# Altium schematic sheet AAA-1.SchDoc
size 594 x 420 mm
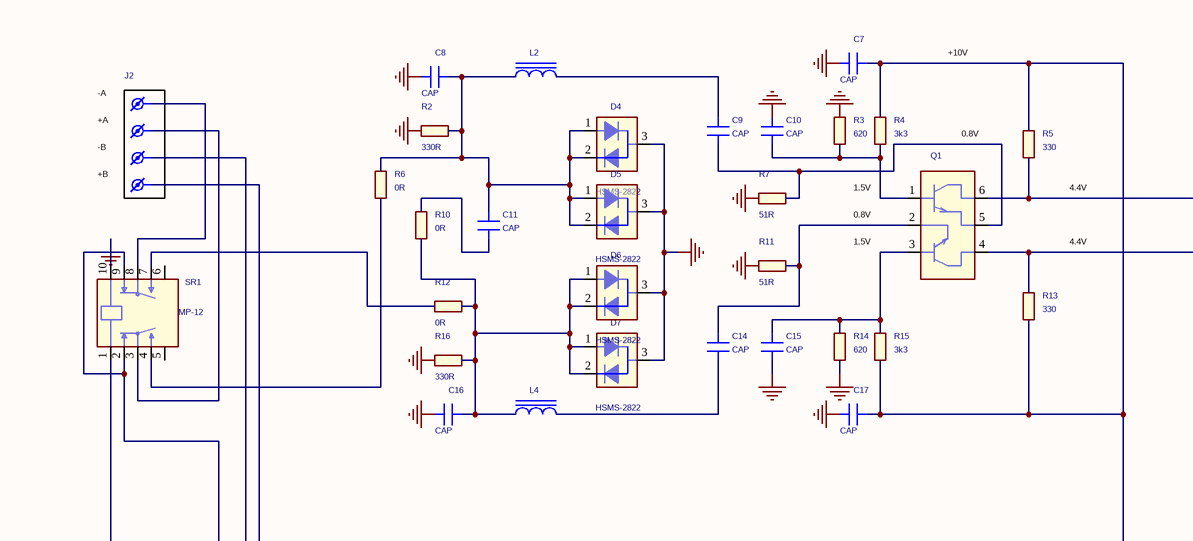
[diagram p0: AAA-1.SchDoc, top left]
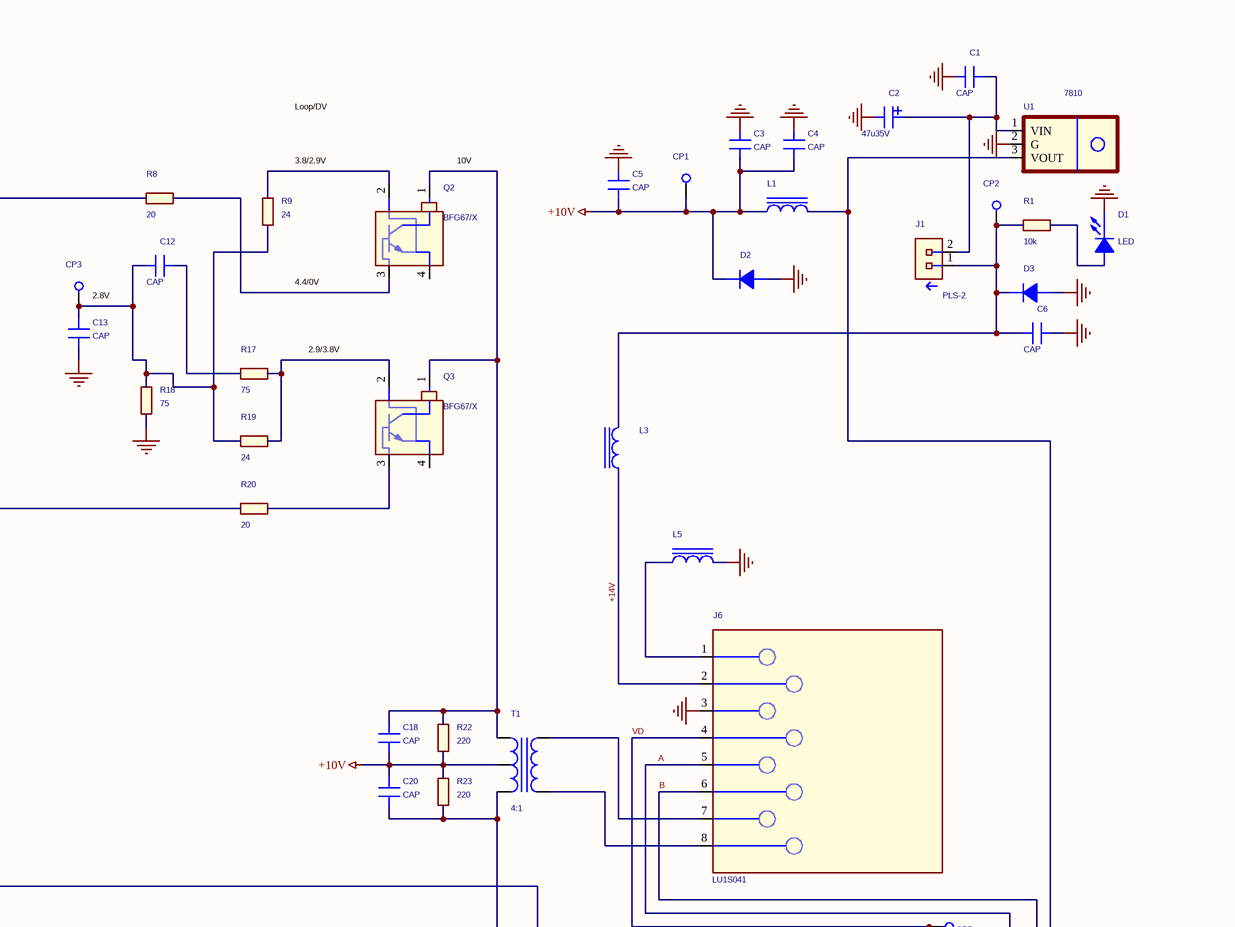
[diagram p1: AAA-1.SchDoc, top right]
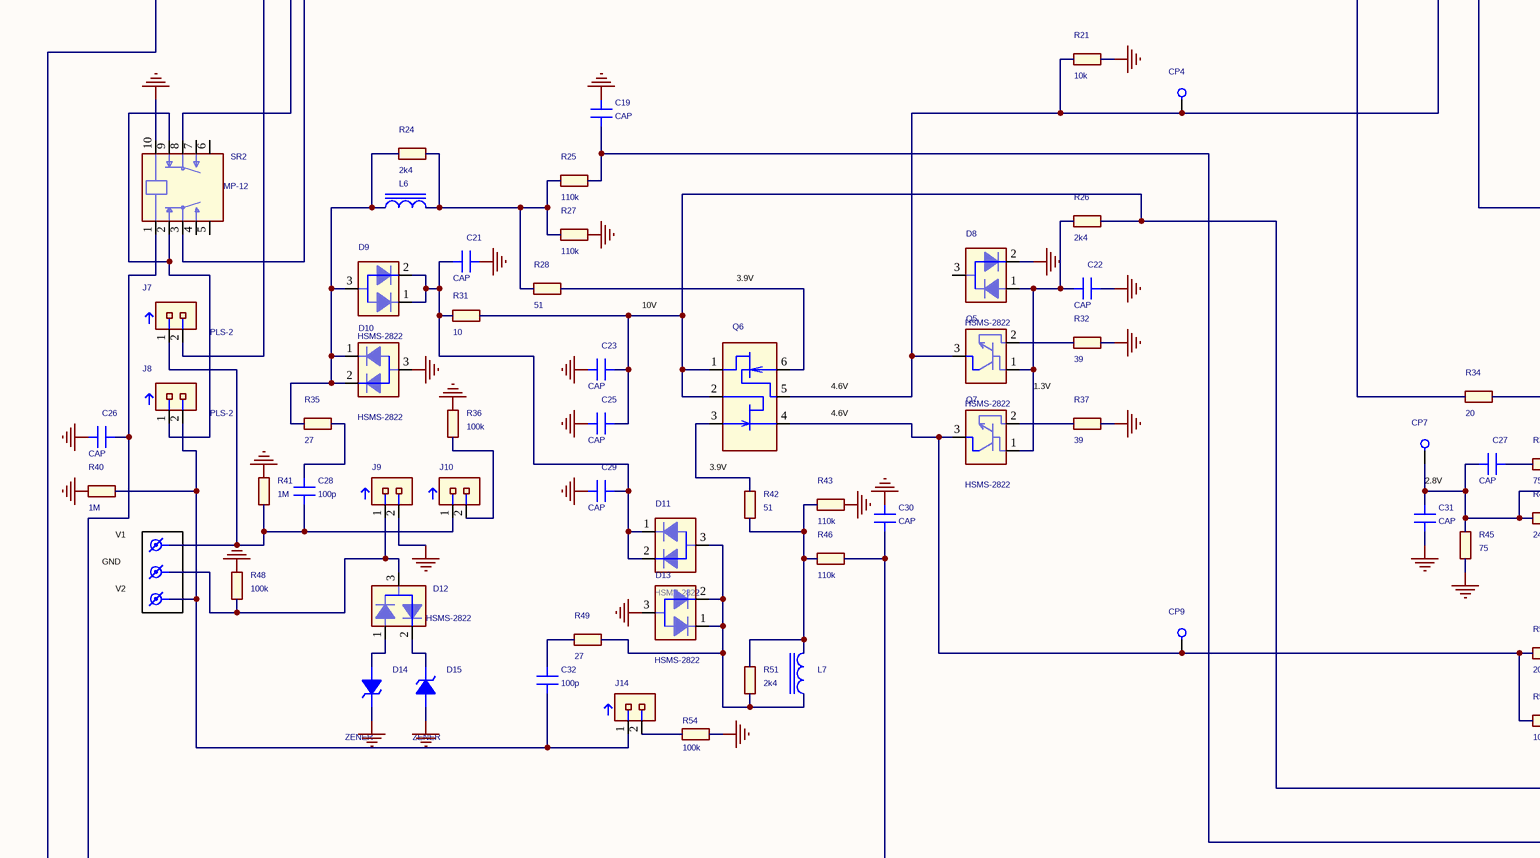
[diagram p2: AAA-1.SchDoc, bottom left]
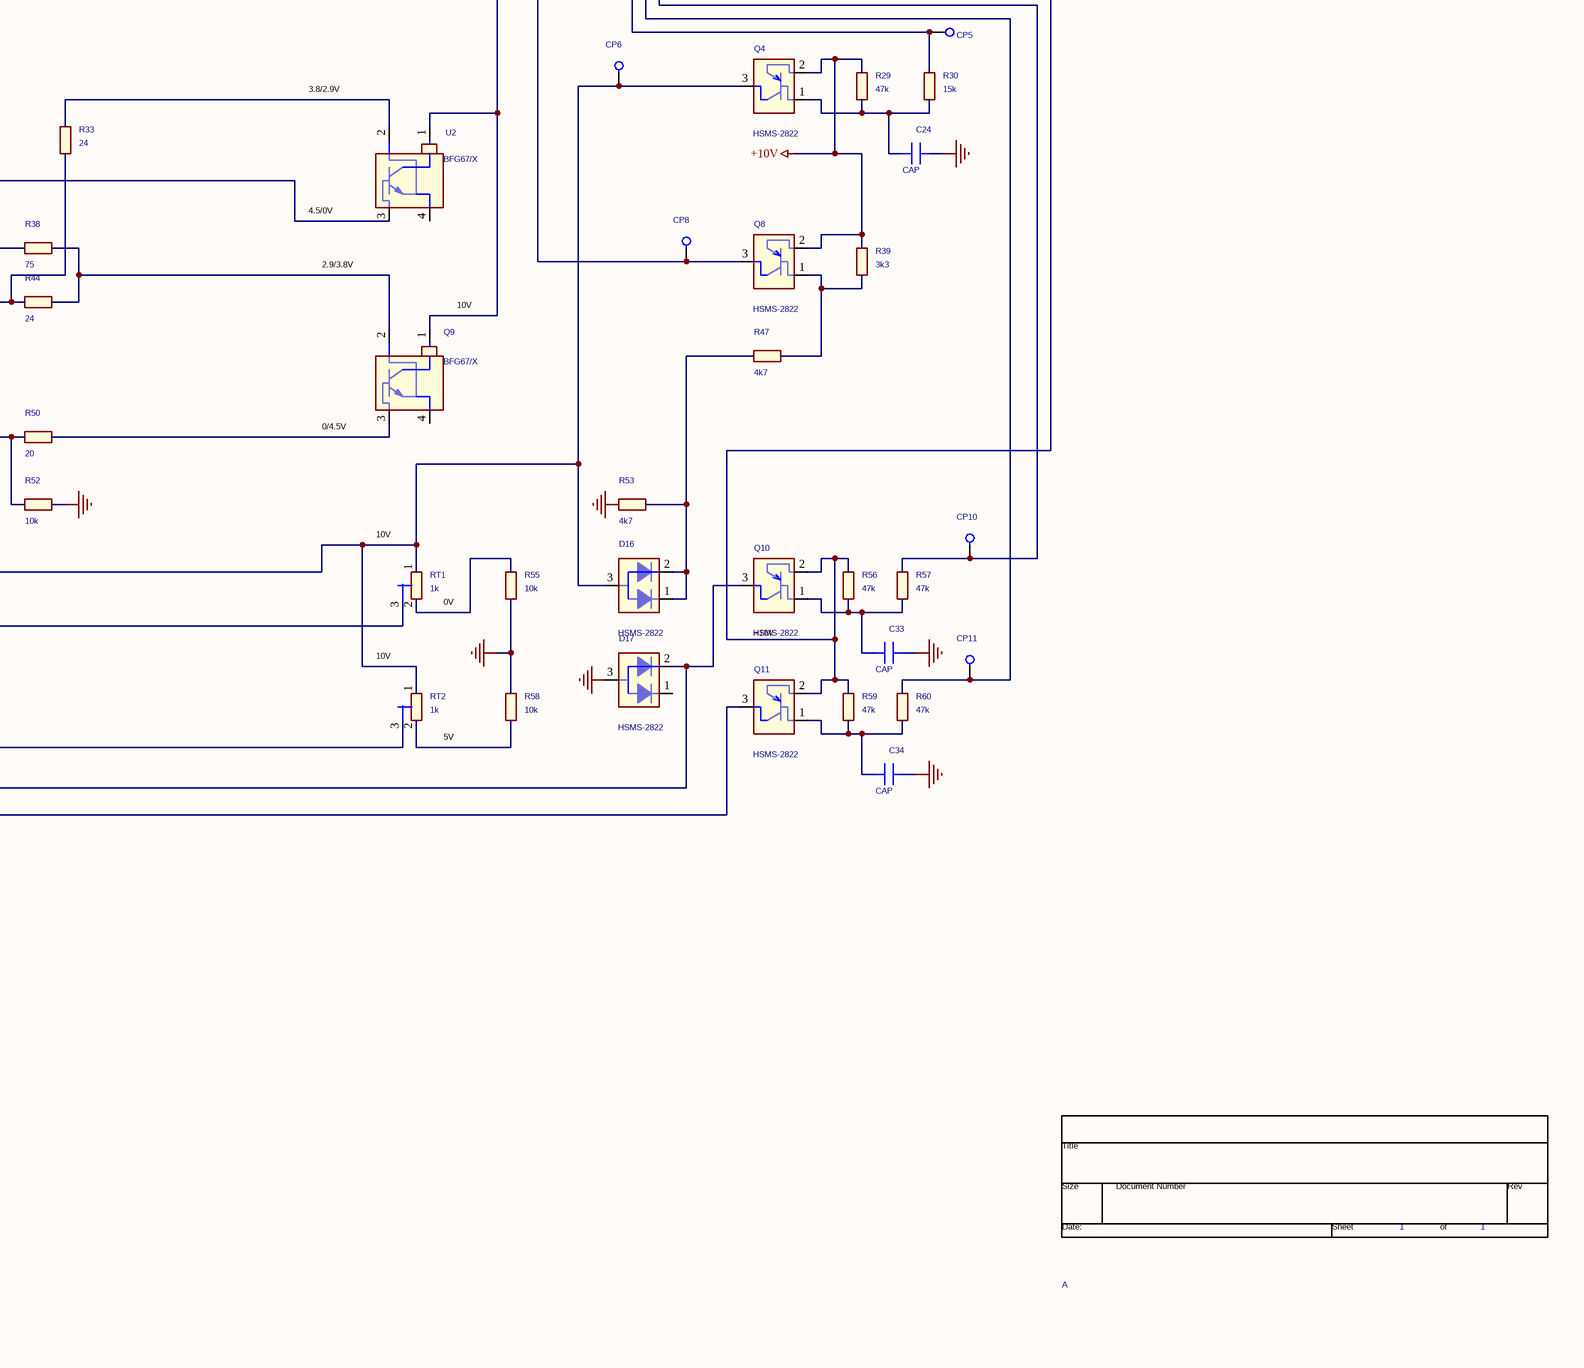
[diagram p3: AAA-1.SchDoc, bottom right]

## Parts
*  Page Count: 1  Page Size: A  (hidden comment: TitleBlock0)  (graphical)
C1  CAP  [-]
C2  47u35V  [-]
C3  CAP  [-]
C4  CAP  [-]
C5  CAP  [-]
C6  CAP  [-]
C7  CAP  [-]
C8  CAP  [-]
C9  CAP  [-]
C10  CAP  [-]
C11  CAP  [-]
C12  CAP  [-]
C13  CAP  [-]
C14  CAP  [-]
C15  CAP  [-]
C16  CAP  [-]
C17  CAP  [-]
C18  CAP  [-]
C19  CAP  [-]
C20  CAP  [-]
C21  CAP  [-]
C22  CAP  [-]
C23  CAP  [-]
C24  CAP  [-]
C25  CAP  [-]
C26  CAP  [-]
C27  CAP  [-]
C28  100p  [-]
C29  CAP  [-]
C30  CAP  [-]
C31  CAP  [-]
C32  100p  [-]
C33  CAP  [-]
C34  CAP  [-]
CP1  -  [-]  (value not drawn)
CP2  -  [-]  (value not drawn)
CP3  -  [-]  (value not drawn)
CP4  -  [-]  (value not drawn)
CP5  -  [-]  (value not drawn)
CP6  -  [-]  (value not drawn)
CP7  -  [-]  (value not drawn)
CP8  -  [-]  (value not drawn)
CP9  -  [-]  (value not drawn)
CP10  -  [-]  (value not drawn)
CP11  -  [-]  (value not drawn)
D1  LED
D2  -  (value not drawn)
D3  -  (value not drawn)
D4  Part Number: HSMS-2822  [SOT-23-3]  (hidden comment: BAV99)
D5  Part Number: HSMS-2822  [SOT-23-3]  (hidden comment: BAV99)
D6  Part Number: HSMS-2822  [SOT-23-3]  (hidden comment: BAV99)
D7  Part Number: HSMS-2822  [SOT-23-3]  (hidden comment: BAV99)
D8  Part Number: HSMS-2822  [SOT-23-3]  (hidden comment: BAV99)
D9  Part Number: HSMS-2822  [SOT-23-3]  (hidden comment: BAV99)
D10  Part Number: HSMS-2822  [SOT-23-3]  (hidden comment: BAV99)
D11  Part Number: HSMS-2822  [SOT-23-3]  (hidden comment: BAV99)
D12  Part Number: HSMS-2822  [SOT-23-3]  (hidden comment: BAV99)
D13  Part Number: HSMS-2822  [SOT-23-3]  (hidden comment: BAV99)
D14  ZENER  [-]
D15  ZENER  [-]
D16  Part Number: HSMS-2822  [SOT-23-3]  (hidden comment: BAV99)
D17  Part Number: HSMS-2822  [SOT-23-3]  (hidden comment: BAV99)
J1  Part Number: PLS-2  [PLS-3]  (hidden comment: -)
J2  -  [-]  (value not drawn)
J3  -  [-]  (value not drawn)
J4  -  [-]  (value not drawn)
J5  -  [-]  (value not drawn)
J6  Part Number: LU1S041  (hidden comment: -)
J7  Part Number: PLS-2  [PLS-3]  (hidden comment: -)
J8  Part Number: PLS-2  [PLS-3]  (hidden comment: -)
J9  -  [PLS-3]  (value not drawn)
J10  -  [PLS-3]  (value not drawn)
J11  -  [-]  (value not drawn)
J12  -  [-]  (value not drawn)
J13  -  [-]  (value not drawn)
J14  -  [PLS-3]  (value not drawn)
L1  100ohm  [-]  (value not drawn)
L2  100ohm  [-]  (value not drawn)
L3  100ohm  [-]  (value not drawn)
L4  100ohm  [-]  (value not drawn)
L5  100ohm  [-]  (value not drawn)
L6  100ohm  [-]  (value not drawn)
L7  100ohm  [-]  (value not drawn)
Q1  BJT-NPN-DOUBLE  [SOT23-6]  (value not drawn)
Q2  -  [SOT-143B]  (value not drawn)
Q3  -  [SOT-143B]  (value not drawn)
Q4  Part Number: HSMS-2822  [SOT-23-3]  (hidden comment: BAV99)
Q5  Part Number: HSMS-2822  [SOT-23-3]  (hidden comment: BAV99)
Q6  BJT-NPN-DOUBLE  [SOT23-6]  (value not drawn)
Q7  Part Number: HSMS-2822  [SOT-23-3]  (hidden comment: BAV99)
Q8  Part Number: HSMS-2822  [SOT-23-3]  (hidden comment: BAV99)
Q9  -  [SOT-143B]  (value not drawn)
Q10  Part Number: HSMS-2822  [SOT-23-3]  (hidden comment: BAV99)
Q11  Part Number: HSMS-2822  [SOT-23-3]  (hidden comment: BAV99)
R1  10k  [-]
R2  330R  [-]
R3  620  [-]
R4  3k3  [-]
R5  330  [-]
R6  0R  [-]
R7  51R  [-]
R8  20  [-]
R9  24  [-]
R10  0R  [-]
R11  51R  [-]
R12  0R  [-]
R13  330  [-]
R14  620  [-]
R15  3k3  [-]
R16  330R  [-]
R17  75  [-]
R18  75  [-]
R19  24  [-]
R20  20  [-]
R21  10k  [-]
R22  220  [-]
R23  220  [-]
R24  2k4  [-]
R25  110k  [-]
R26  2k4  [-]
R27  110k  [-]
R28  51  [-]
R29  47k  [-]
R30  15k  [-]
R31  10  [-]
R32  39  [-]
R33  24  [-]
R34  20  [-]
R35  27  [-]
R36  100k  [-]
R37  39  [-]
R38  75  [-]
R39  3k3  [-]
R40  1M  [-]
R41  1M  [-]
R42  51  [-]
R43  110k  [-]
R44  24  [-]
R45  75  [-]
R46  110k  [-]
R47  4k7  [-]
R48  100k  [-]
R49  27  [-]
R50  20  [-]
R51  2k4  [-]
R52  10k  [-]
R53  4k7  [-]
R54  100k  [-]
R55  10k  [-]
R56  47k  [-]
R57  47k  [-]
R58  10k  [-]
R59  47k  [-]
R60  47k  [-]
RT1  1k  [-]
RT2  1k  [-]
SR1  MP-12  [DIP-10]
SR2  MP-12  [DIP-10]
T1  4:1  [-]
U1  Part Number: 7810  (hidden comment: -5V)
U2  -  [SOT-143B]  (value not drawn)

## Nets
+10V: C3.1 C4.1 C5.1 C18.1 C20.2 CP1.1(TP) D2.2(K) L1.1 L1.2 Q4.2 Q8.2 Q10.2 Q11.2 R22.1 R23.2 R29.2 R39.2 R56.2 R59.2 T1.5 U1.3(VOUT)
GND: C1.1 C2.2 C3.2 C4.2 C5.2 C6.2 C7.1 C8.1 C10.2 C13.1 C15.1 C16.1 C17.1 C19.2 C21.2 C22.2 C23.1 C24.2 C25.1 C26.1 C29.1 C30.2 C31.1 C33.2 C34.2 D1.2(CATHODE) D2.1(A) D3.1(A) D4.3 D5.3 D6.3 D7.3 D8.2 D10.3 D13.3 D14.2(CATHODE) D15.1(ANODE) D17.3 J6.3(TCT) J9.2 L5.2 R2.2 R3.2 R7.2 R11.2 R14.1 R16.2 R18.1 R21.1 R27.1 R32.1 R36.2 R37.1 R40.2 R41.2 R43.1 R45.1 R48.1 R52.1 R53.2 R54.1 R55.1 R58.2 SR1.10(COIL2) SR2.10(COIL2) U1.2(G)
+14V: J6.2(TX-) L3.1
A: CP11.1(TP) J6.5(NC2) R60.2
B: CP10.1(TP) J6.6(RCT) R57.2
VD: CP5.1(TP) J6.4(NC1) R30.2
NetC1_2: C1.2 C2.1 J1.2 U1.1(VIN)
NetC6_1: C6.1 CP2.1(TP) D3.2(K) J1.1 L3.2 R1.2
NetC7_2: C7.2 C17.2 CP8.1(TP) Q8.3 R4.2 R5.2 R13.1 R15.1
NetC8_2: C8.2 C11.2 D4.1 D4.2 D5.1 D5.2 L2.1 R2.1 R6.2
NetC9_1: C9.1 Q1.5(e1) R7.1
NetC9_2: C9.2 L2.2
NetC10_1: C10.1 Q1.1(b1) R3.1 R4.1
NetC11_1: C11.1 R10.2
NetC12_1: C12.1 C13.2 CP3.1(TP) R9.1 R18.2 R19.2
NetC12_2: C12.2 R17.2
NetC14_1: C14.1 L4.2
NetC14_2: C14.2 Q1.2(e2) R11.1
NetC15_2: C15.2 Q1.3(b2) R14.2 R15.2
NetC16_2: C16.2 D6.1 D6.2 D7.1 D7.2 L4.1 R10.1 R12.1 R16.1
NetC18_2: C18.2 Q2.1(C) Q3.1(C) R22.2 T1.6
NetC19_1: C19.1 R25.1 RT1.3
NetC20_1: C20.1 Q9.1(C) R23.1 T1.4 U2.1(C)
NetC21_1: C21.1 C29.2 D9.1 D9.2 D11.1 D11.2 R31.2
NetC22_1: C22.1 D8.1 Q5.1 Q7.1 R26.2
NetC23_2: C23.2 C25.2 CP6.1(TP) D16.3 Q4.3 Q6.1(b1) Q6.2(e2) R26.1 R31.1 RT1.1 RT2.1
NetC24_1: C24.1 Q4.1 R29.1 R30.1
NetC26_2: C26.2 D17.2 Q10.3 SR2.1(COIL1)
NetC27_1: C27.1 C31.2 CP7.1(TP) R33.1 R44.2 R45.2
NetC27_2: C27.2 R38.2
NetC28_1: C28.1 J7.1 J10.1 J11.1 R41.1
NetC28_2: C28.2 R35.1
NetC30_1: C30.1 R46.1 RT2.3
NetC32_1: C32.1 J8.2 J13.1 J14.1 R40.1
NetC32_2: C32.2 R49.2
NetC33_1: C33.1 Q10.1 R56.1 R57.1
NetC34_1: C34.1 Q11.1 R59.1 R60.1
NetCP4_1: CP4.1(TP) Q5.3 Q6.5(e1) R20.2 R21.2
NetCP9_1: CP9.1(TP) Q6.4(c2) Q7.3 R50.2 R52.2
NetD1_1: D1.1(ANODE) R1.1
NetD9_3: D9.3 D10.1 D10.2 L6.1 R24.2 R35.2
NetD11_3: D11.3 D13.1 D13.2 L7.1 R49.1 R51.1
NetD12_1: D12.1 D14.1(ANODE)
NetD12_2: D12.2 D15.2(CATHODE)
NetD12_3: D12.3 J9.1 J12.1 R48.2
NetD16_1: D16.1 D16.2 R47.2 R53.1
NetJ2_1: J2.1 SR1.8(SC2)
NetJ3_1: J3.1 SR1.3(SC1)
NetJ4_1: J4.1 SR2.8(SC2)
NetJ5_1: J5.1 SR2.3(SC1)
NetJ6_1: J6.1(TX+) L5.1
NetJ6_7: J6.7(RX+) T1.1
NetJ6_8: J6.8(RX-) T1.3
NetJ7_2: J7.2 SR1.2(S1-1) SR1.9(SC2-1)
NetJ8_1: J8.1 SR2.2(S1-1) SR2.9(SC2-1)
NetJ10_2: J10.2 R36.1
NetJ14_2: J14.2 R54.2
NetL6_2: L6.2 R24.1 R25.2 R27.2 R28.2
NetL7_2: L7.2 R42.1 R43.2 R46.2 R51.2
NetQ1_4: Q1.4(c2) R13.2 R34.2
NetQ1_6: Q1.6(c1) R5.1 R8.2
NetQ2_2: Q2.2(E1) R9.2
NetQ2_3: Q2.3(B) R8.1
NetQ3_2: Q3.2(E1) R17.1 R19.1
NetQ3_3: Q3.3(B) R20.1
NetQ5_2: Q5.2 R32.2
NetQ6_3: Q6.3(b2) R42.2
NetQ6_6: Q6.6(c1) R28.1
NetQ7_2: Q7.2 R37.2
NetQ8_1: Q8.1 R39.1 R47.1
NetQ9_2: Q9.2(E1) R38.1 R44.1
NetQ9_3: Q9.3(B) R50.1
NetQ11_3: Q11.3 SR1.1(COIL1)
NetR6_1: R6.1 SR1.4(S1-2)
NetR12_2: R12.2 SR1.7(S2-2)
NetR33_2: R33.2 U2.2(E1)
NetR34_1: R34.1 U2.3(B)
NetR55_2: R55.2 RT1.2
NetR58_1: R58.1 RT2.2

Not connected (* = marked no-connect by the designer): D8 3; D17 1; Q2 4(E2); Q3 4(E2); Q9 4(E2); SR1 5(NC1) 6(NC2); SR2 4(S1-2) 5(NC1) 6(NC2) 7(S2-2); U2 4(E2)

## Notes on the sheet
- +10V
- -A
- +A
- 0.8V
- Loop/DV
- -B
- +B
- 1.5V
- (near R5) 4.4V
- (near R9) 3.8/2.9V
- (near Q2) 10V
- 4.4V
- 2.8V
- 4.4/0V
- 2.9/3.8V
- 10V
- 3.9V
- 3.8/2.9V
- 4.6V
- 1.3V
- 4.5/0V
- V1
- (near Q9) 10V
- GND
- V2
- (near Q9) 0/4.5V
- (near RT1) 10V
- (near RT2) 10V
- (near RT1) 0V
- (near RT2) 5V

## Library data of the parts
C1 C3-C34 = CAP: Designation: Capacitor
C2 = CAP_POLAR: Designation: Polar Capacitor
CP1-CP11 = T POINT R: Part Number: Constructive; Designation: Terminal Point
D2 D3 = DIODE
D4-D8 D12 = BAV99: Manufacturer: Agilent_Technology; Designation: Shottky_Diode_Array
D9-D11 D13 D16 D17 = BAV99_0: Manufacturer: Agilent_Technology; Designation: Shottky_Diode_Array
D14 D15 = ZENER: Designation: Zener_Diode
J1 J7 J8 = PLS-3_0: Designation: 3-pin Header Plug
J2-J5 J11-J13 = CLEMMA
J6 = Ethernet_LU1S041_0: Manufacturer: Bothhand USA; Designation: Ethernet PCB Jack
J9 J10 J14 = PLS-3_0: Part Number: PLS-2; Designation: 3-pin Header Plug
L1-L7 = CHOKE: Designation: Ferrite Choke
Q2 Q3 Q9 U2 = BFG67/X: Designation: NPN_BJT
Q4 Q8 Q10 Q11 = BAV99_2: Manufacturer: Agilent_Technology; Designation: Shottky_Diode_Array
Q5 Q7 = BAV99_1: Manufacturer: Agilent_Technology; Designation: Shottky_Diode_Array
Q6 = BJT-NPN-DOUBLE_1
R1-R60 = RESISTOR
RT1 RT2 = TRIMM_RES: Designation: Trimmer Resistor
SR1 SR2 = MP-12: Manufacturer: Sun Hold; Designation: Double Relay SPDT
T1 = TRANS_0: Designation: Transformer
U1 = LVR-/TO-220_0: Designation: Negative Linear Voltage Regulator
